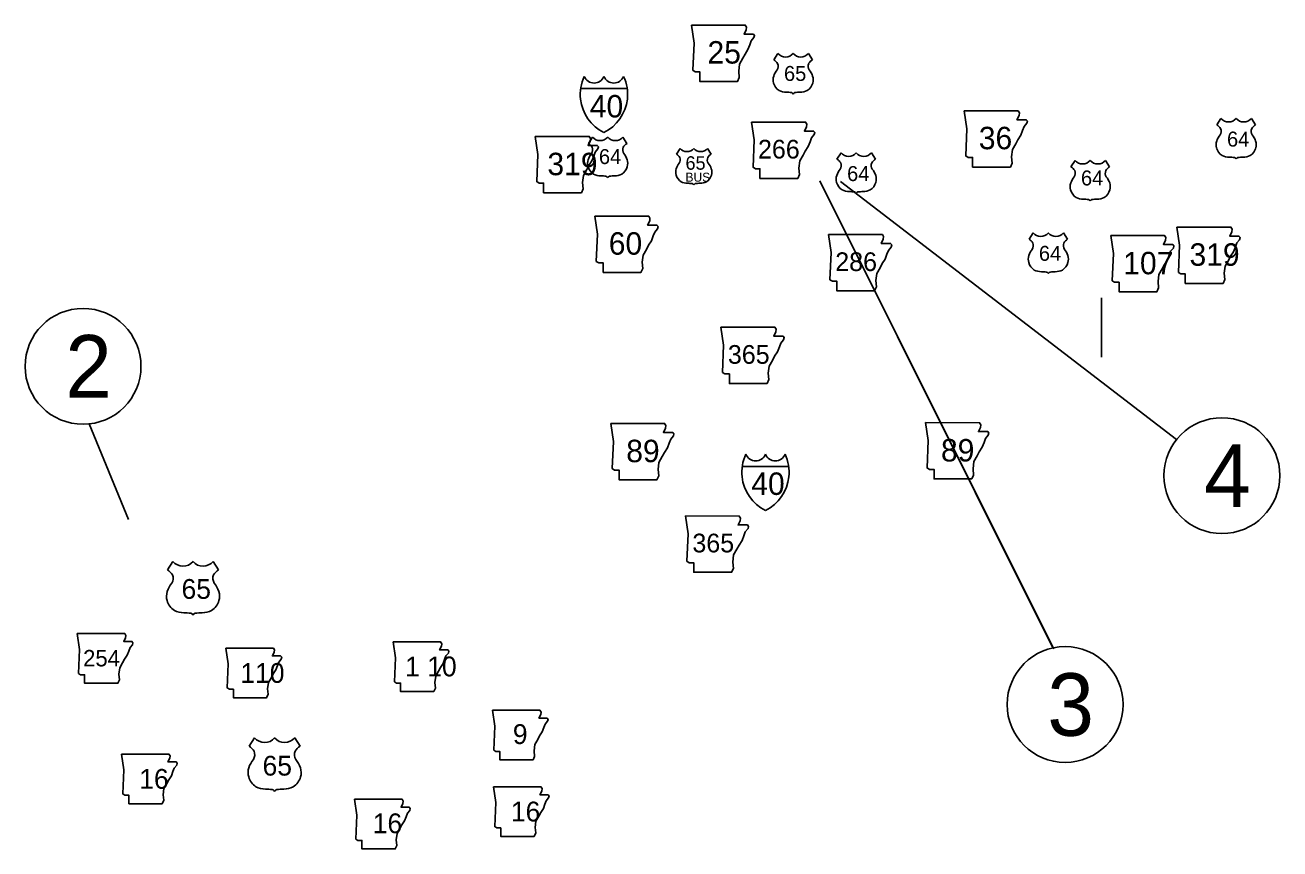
# Model space of a CAD drawing. Extents: x 840176 to 859715, y 1589036 to 1600368.
# Drawn here: x 844901 to 848918, y 1591719 to 1594357 of the extents above; entities that cross this region are included whole.
import ezdxf

# ---------------------------------------------------------------- set-up
doc = ezdxf.new("R2010")
doc.units = 0
for name, color, linetype in [('2', 7, 'Continuous'), ('6', 7, 'Continuous'), ('Default', 7, 'Continuous'), ('DSN_DRFT_Border', 7, 'Continuous'), ('DSN_DRFT_Common-Line', 7, 'Continuous'), ('SHET_Stamp-Prelim', 7, 'Continuous')]:
    doc.layers.add(name, color=color, linetype=linetype)

msp = doc.modelspace()

# ---------------------------------------------------------------- linework, layer by layer
at = {"layer": '2'}
for points in [[(847034.2, 1594357.5), (847042.8, 1594299.9), (847039, 1594212.6), (847046.6, 1594207.8), (847061, 1594207.8), (847061, 1594177.1), (847182, 1594177.1), (847187.7, 1594189.5), (847185.8, 1594209.7), (847188.7, 1594232.7), (847199.2, 1594251), (847206, 1594264.4), (847215.5, 1594278.8), (847221.3, 1594294.2), (847226.1, 1594306.6), (847234.7, 1594317.2), (847236.7, 1594323.9), (847232.8, 1594328.7), (847203.1, 1594328.7), (847209.8, 1594342.1), (847210.8, 1594350.8), (847206.8, 1594357.4)], [(847907.6, 1594083.3), (847916.2, 1594025.7), (847912.4, 1593938.3), (847920.1, 1593933.5), (847934.5, 1593933.5), (847934.5, 1593902.8), (848055.4, 1593902.8), (848061.1, 1593915.3), (848059.2, 1593935.5), (848062.1, 1593958.5), (848072.7, 1593976.7), (848079.4, 1593990.2), (848089, 1594004.6), (848094.7, 1594019.9), (848099.5, 1594032.4), (848108.2, 1594042.9), (848110.1, 1594049.7), (848106.2, 1594054.5), (848076.5, 1594054.5), (848083.2, 1594067.9), (848084.2, 1594076.5), (848080.2, 1594083.2)], [(847227, 1594047), (847235.7, 1593989.4), (847231.8, 1593902.1), (847239.5, 1593897.3), (847253.9, 1593897.3), (847253.9, 1593866.5), (847374.8, 1593866.5), (847380.6, 1593879), (847378.7, 1593899.2), (847381.5, 1593922.2), (847392.1, 1593940.4), (847398.8, 1593953.9), (847408.4, 1593968.3), (847414.2, 1593983.6), (847419, 1593996.1), (847427.6, 1594006.7), (847429.5, 1594013.4), (847425.7, 1594018.2), (847395.9, 1594018.2), (847402.6, 1594031.6), (847403.6, 1594040.2), (847399.6, 1594046.9)], [(846534.5, 1594001), (846543.1, 1593943.4), (846539.3, 1593856.1), (846547, 1593851.3), (846561.4, 1593851.3), (846561.4, 1593820.6), (846682.3, 1593820.6), (846688.1, 1593833.1), (846686.1, 1593853.2), (846689, 1593876.2), (846699.6, 1593894.5), (846706.3, 1593907.9), (846715.9, 1593922.3), (846721.6, 1593937.7), (846726.4, 1593950.1), (846735.1, 1593960.7), (846737, 1593967.4), (846733.2, 1593972.2), (846703.4, 1593972.2), (846710.1, 1593985.6), (846711.1, 1593994.3), (846707.1, 1594000.9)], [(846725.2, 1593745.6), (846733.8, 1593688), (846730, 1593600.7), (846737.7, 1593595.9), (846752.1, 1593595.9), (846752.1, 1593565.2), (846873, 1593565.2), (846878.7, 1593577.6), (846876.8, 1593597.8), (846879.7, 1593620.8), (846890.3, 1593639.1), (846897, 1593652.5), (846906.6, 1593666.9), (846912.3, 1593682.3), (846917.1, 1593694.7), (846925.8, 1593705.3), (846927.7, 1593712), (846923.8, 1593716.8), (846894.1, 1593716.8), (846900.8, 1593730.2), (846901.8, 1593738.9), (846897.8, 1593745.5)], [(848588.7, 1593710.4), (848597.3, 1593652.8), (848593.5, 1593565.5), (848601.1, 1593560.7), (848615.5, 1593560.7), (848615.5, 1593530), (848736.4, 1593530), (848742.2, 1593542.5), (848740.3, 1593562.6), (848743.2, 1593585.7), (848753.7, 1593603.9), (848760.4, 1593617.3), (848770, 1593631.7), (848775.8, 1593647.1), (848780.6, 1593659.5), (848789.2, 1593670.1), (848791.1, 1593676.8), (848787.3, 1593681.6), (848757.6, 1593681.6), (848764.3, 1593695.1), (848765.2, 1593703.7), (848761.3, 1593710.3)], [(847473.1, 1593686.7), (847481.7, 1593629.1), (847477.9, 1593541.7), (847485.6, 1593536.9), (847500, 1593536.9), (847500, 1593506.2), (847620.9, 1593506.2), (847626.6, 1593518.7), (847624.7, 1593538.9), (847627.6, 1593561.9), (847638.2, 1593580.1), (847644.9, 1593593.6), (847654.5, 1593608), (847660.2, 1593623.3), (847665, 1593635.8), (847673.7, 1593646.4), (847675.6, 1593653.1), (847671.8, 1593657.9), (847642, 1593657.9), (847648.7, 1593671.3), (847649.7, 1593679.9), (847645.7, 1593686.6)], [(848376.6, 1593683.6), (848385.2, 1593626), (848381.4, 1593538.7), (848389, 1593533.9), (848403.4, 1593533.9), (848403.4, 1593503.2), (848524.4, 1593503.2), (848530.1, 1593515.7), (848528.2, 1593535.8), (848531.1, 1593558.9), (848541.6, 1593577.1), (848548.4, 1593590.5), (848558, 1593604.9), (848563.7, 1593620.3), (848568.5, 1593632.8), (848577.1, 1593643.3), (848579.1, 1593650), (848575.2, 1593654.8), (848545.5, 1593654.8), (848552.2, 1593668.3), (848553.2, 1593676.9), (848549.2, 1593683.5)], [(847128.9, 1593389.9), (847137.6, 1593332.3), (847133.7, 1593244.9), (847141.4, 1593240.1), (847155.8, 1593240.1), (847155.8, 1593209.4), (847276.7, 1593209.4), (847282.5, 1593221.9), (847280.6, 1593242.1), (847283.4, 1593265.1), (847294, 1593283.3), (847300.7, 1593296.8), (847310.3, 1593311.2), (847316.1, 1593326.5), (847320.9, 1593339), (847329.5, 1593349.5), (847331.4, 1593356.3), (847327.6, 1593361.1), (847297.8, 1593361.1), (847304.6, 1593374.5), (847305.5, 1593383.1), (847301.5, 1593389.8)], [(846776.1, 1593081.6), (846784.7, 1593024), (846780.9, 1592936.7), (846788.5, 1592931.9), (846802.9, 1592931.9), (846802.9, 1592901.2), (846923.9, 1592901.2), (846929.6, 1592913.6), (846927.7, 1592933.8), (846930.6, 1592956.8), (846941.1, 1592975.1), (846947.8, 1592988.5), (846957.4, 1593002.9), (846963.2, 1593018.2), (846968, 1593030.7), (846976.6, 1593041.3), (846978.6, 1593048), (846974.7, 1593052.8), (846945, 1593052.8), (846951.7, 1593066.2), (846952.6, 1593074.9), (846948.7, 1593081.5)], [(847784.2, 1593084), (847792.8, 1593026.4), (847789, 1592939.1), (847796.7, 1592934.3), (847811, 1592934.3), (847811, 1592903.6), (847932, 1592903.6), (847937.7, 1592916), (847935.8, 1592936.2), (847938.7, 1592959.2), (847949.2, 1592977.5), (847956, 1592990.9), (847965.6, 1593005.3), (847971.3, 1593020.6), (847976.1, 1593033.1), (847984.8, 1593043.7), (847986.7, 1593050.4), (847982.8, 1593055.2), (847953.1, 1593055.2), (847959.8, 1593068.6), (847960.8, 1593077.3), (847956.8, 1593083.9)], [(847015, 1592785.1), (847023.6, 1592727.5), (847019.8, 1592640.2), (847027.5, 1592635.4), (847041.9, 1592635.4), (847041.9, 1592604.7), (847162.8, 1592604.7), (847168.6, 1592617.2), (847166.6, 1592637.3), (847169.5, 1592660.3), (847180.1, 1592678.6), (847186.8, 1592692), (847196.4, 1592706.4), (847202.1, 1592721.8), (847206.9, 1592734.2), (847215.6, 1592744.8), (847217.5, 1592751.5), (847213.7, 1592756.3), (847183.9, 1592756.3), (847190.6, 1592769.7), (847191.6, 1592778.4), (847187.6, 1592785)]]:
    msp.add_lwpolyline(points, close=True, dxfattribs=at)
at = {"layer": '6'}
for p, q in [((847311.4, 1594266.6), (847298.3, 1594246.4)), ((847408.8, 1594266.6), (847421.8, 1594246.4)), ((848729.5, 1594058.5), (848716.4, 1594038.2)), ((848826.9, 1594058.5), (848840, 1594038.2)), ((846717.7, 1593998.7), (846704.6, 1593978.4)), ((846815, 1593998.7), (846828.1, 1593978.4)), ((846998.2, 1593962.5), (846986.4, 1593944.2)), ((847085.8, 1593962.5), (847097.6, 1593944.2)), ((847513.3, 1593948.3), (847500.2, 1593928.1)), ((847610.7, 1593948.3), (847623.8, 1593928.1)), ((848262.4, 1593924), (848249.3, 1593903.7)), ((848359.7, 1593924), (848372.8, 1593903.7)), ((848128.3, 1593691.7), (848115.2, 1593671.4)), ((848225.6, 1593691.7), (848238.7, 1593671.4))]:
    msp.add_line(p, q, dxfattribs=at)
for centre, radius, start, end in [((847335.8, 1594287.1), 31.9, 220.075, 319.6701), ((847384.4, 1594287.1), 31.9, 220.3299, 319.925), ((847349.7, 1594178.2), 54.4, 138.9565, 162.6913), ((847281.2, 1594217), 34, 30.7809, 59.9883), ((847288.7, 1594225.9), 23.3, 328.8105, 21.2108), ((847431.5, 1594225.9), 23.3, 158.7892, 211.1895), ((847438.9, 1594217), 34, 120.0117, 149.2191), ((847370.5, 1594178.2), 54.4, 17.3087, 41.0435), ((847331.7, 1594182.6), 35.9, 160.9576, 197.3819), ((847337.6, 1594182.7), 41.6, 195.1074, 237.1312), ((847382.6, 1594182.7), 41.6, 302.8688, 344.8926), ((847388.5, 1594182.6), 35.9, 342.6181, 19.0424), ((847338.3, 1594195.8), 53.4, 244.0771, 269.5779), ((847339.6, 1594044.6), 97.8, 81.1942, 90.9539), ((847351.8, 1594132.3), 9.37, 28.0342, 72.9864), ((847368.4, 1594132.3), 9.37, 107.0136, 151.9658), ((847380.6, 1594044.6), 97.8, 89.0461, 98.8058), ((847381.8, 1594195.8), 53.4, 270.4221, 295.9229), ((848753.9, 1594079), 31.9, 220.075, 319.6701), ((848802.5, 1594079), 31.9, 220.3299, 319.925), ((848699.3, 1594008.8), 34, 30.7809, 59.9883), ((848706.8, 1594017.8), 23.3, 328.8105, 21.2108), ((848849.6, 1594017.8), 23.3, 158.7892, 211.1895), ((848857.1, 1594008.8), 34, 120.0117, 149.2191), ((846687.5, 1593949), 34, 30.7809, 59.9883), ((846742.1, 1594019.2), 31.9, 220.075, 319.6701), ((846790.7, 1594019.2), 31.9, 220.3299, 319.925), ((846845.2, 1593949), 34, 120.0117, 149.2191), ((848749.8, 1593974.5), 35.9, 160.9576, 197.3819), ((848767.8, 1593970), 54.4, 138.9565, 162.6913), ((848788.6, 1593970), 54.4, 17.3087, 41.0435), ((848806.6, 1593974.5), 35.9, 342.6181, 19.0424), ((846756, 1593910.2), 54.4, 138.9565, 162.6913), ((846695, 1593958), 23.3, 328.8105, 21.2108), ((846837.8, 1593958), 23.3, 158.7892, 211.1895), ((846776.8, 1593910.2), 54.4, 17.3087, 41.0435), ((846971, 1593917.8), 30.6, 30.7809, 59.9883), ((846977.7, 1593925.9), 21, 328.8105, 21.2108), ((847020.1, 1593980.9), 28.7, 220.075, 319.6701), ((847063.8, 1593980.9), 28.7, 220.3299, 319.925), ((847106.2, 1593925.9), 21, 158.7892, 211.1895), ((847113, 1593917.8), 30.6, 120.0117, 149.2191), ((847483.1, 1593898.7), 34, 30.7809, 59.9883), ((847537.7, 1593968.9), 31.9, 220.075, 319.6701), ((847586.3, 1593968.9), 31.9, 220.3299, 319.925), ((847640.9, 1593898.7), 34, 120.0117, 149.2191), ((848755.7, 1593974.6), 41.6, 195.1074, 237.1312), ((848756.5, 1593987.7), 53.4, 244.0771, 269.5779), ((848757.7, 1593836.5), 97.8, 81.1942, 90.9539), ((848769.9, 1593924.2), 9.37, 28.0342, 72.9864), ((848786.5, 1593924.2), 9.37, 107.0136, 151.9658), ((848798.7, 1593836.5), 97.8, 89.0461, 98.8058), ((848799.9, 1593987.7), 53.4, 270.4221, 295.9229), ((848800.7, 1593974.6), 41.6, 302.8688, 344.8926), ((846738, 1593914.7), 35.9, 160.9576, 197.3819), ((846743.9, 1593914.8), 41.6, 195.1074, 237.1312), ((846788.9, 1593914.8), 41.6, 302.8688, 344.8926), ((846794.7, 1593914.7), 35.9, 342.6181, 19.0424), ((847016.4, 1593886.9), 32.3, 160.9576, 197.3819), ((847032.6, 1593882.9), 49, 138.9565, 162.6913), ((847051.3, 1593882.9), 49, 17.3087, 41.0435), ((847067.5, 1593886.9), 32.3, 342.6181, 19.0424), ((847551.6, 1593859.9), 54.4, 138.9565, 162.6913), ((847490.6, 1593907.7), 23.3, 328.8105, 21.2108), ((847633.4, 1593907.7), 23.3, 158.7892, 211.1895), ((847572.4, 1593859.9), 54.4, 17.3087, 41.0435), ((848232.2, 1593874.3), 34, 30.7809, 59.9883), ((848239.7, 1593883.3), 23.3, 328.8105, 21.2108), ((848286.8, 1593944.5), 31.9, 220.075, 319.6701), ((848335.4, 1593944.5), 31.9, 220.3299, 319.925), ((848382.5, 1593883.3), 23.3, 158.7892, 211.1895), ((848389.9, 1593874.3), 34, 120.0117, 149.2191), ((846744.6, 1593927.9), 53.4, 244.0771, 269.5779), ((846745.9, 1593776.7), 97.8, 81.1942, 90.9539), ((846758.1, 1593864.4), 9.37, 28.0342, 72.9864), ((846774.7, 1593864.4), 9.37, 107.0136, 151.9658), ((846786.9, 1593776.7), 97.8, 89.0461, 98.8058), ((846788.1, 1593927.9), 53.4, 270.4221, 295.9229), ((847021.7, 1593887), 37.4, 195.1074, 237.1312), ((847022.4, 1593898.7), 48.1, 244.0771, 269.5779), ((847023.5, 1593762.7), 88, 81.1942, 90.9539), ((847034.5, 1593841.6), 8.44, 28.0342, 72.9864), ((847049.4, 1593841.6), 8.44, 107.0136, 151.9658), ((847060.4, 1593762.7), 88, 89.0461, 98.8058), ((847061.5, 1593898.7), 48.1, 270.4221, 295.9229), ((847062.2, 1593887), 37.4, 302.8688, 344.8926), ((847533.6, 1593864.3), 35.9, 160.9576, 197.3819), ((847539.5, 1593864.4), 41.6, 195.1074, 237.1312), ((847584.5, 1593864.4), 41.6, 302.8688, 344.8926), ((847590.4, 1593864.3), 35.9, 342.6181, 19.0424), ((848282.7, 1593840), 35.9, 160.9576, 197.3819), ((848300.7, 1593835.5), 54.4, 138.9565, 162.6913), ((848321.5, 1593835.5), 54.4, 17.3087, 41.0435), ((848339.4, 1593840), 35.9, 342.6181, 19.0424), ((847540.3, 1593877.5), 53.4, 244.0771, 269.5779), ((847541.5, 1593726.3), 97.8, 81.1942, 90.9539), ((847553.7, 1593814), 9.37, 28.0342, 72.9864), ((847570.3, 1593814), 9.37, 107.0136, 151.9658), ((847582.5, 1593726.3), 97.8, 89.0461, 98.8058), ((847583.7, 1593877.5), 53.4, 270.4221, 295.9229), ((848288.6, 1593840.1), 41.6, 195.1074, 237.1312), ((848333.6, 1593840.1), 41.6, 302.8688, 344.8926), ((848289.3, 1593853.2), 53.4, 244.0771, 269.5779), ((848290.6, 1593702), 97.8, 81.1942, 90.9539), ((848302.8, 1593789.7), 9.37, 28.0342, 72.9864), ((848319.3, 1593789.7), 9.37, 107.0136, 151.9658), ((848331.6, 1593702), 97.8, 89.0461, 98.8058), ((848332.8, 1593853.2), 53.4, 270.4221, 295.9229), ((848152.7, 1593712.2), 31.9, 220.075, 319.6701), ((848201.2, 1593712.2), 31.9, 220.3299, 319.925), ((848098.1, 1593642), 34, 30.7809, 59.9883), ((848105.6, 1593651), 23.3, 328.8105, 21.2108), ((848248.3, 1593651), 23.3, 158.7892, 211.1895), ((848255.8, 1593642), 34, 120.0117, 149.2191), ((848148.6, 1593607.7), 35.9, 160.9576, 197.3819), ((848166.5, 1593603.2), 54.4, 138.9565, 162.6913), ((848187.4, 1593603.2), 54.4, 17.3087, 41.0435), ((848205.3, 1593607.7), 35.9, 342.6181, 19.0424), ((848154.4, 1593607.8), 41.6, 195.1074, 237.1312), ((848155.2, 1593620.9), 53.4, 244.0771, 269.5779), ((848156.4, 1593469.7), 97.8, 81.1942, 90.9539), ((848197.4, 1593469.7), 97.8, 89.0461, 98.8058), ((848198.7, 1593620.9), 53.4, 270.4221, 295.9229), ((848199.5, 1593607.8), 41.6, 302.8688, 344.8926), ((848168.7, 1593557.4), 9.37, 28.0342, 72.9864), ((848185.2, 1593557.4), 9.37, 107.0136, 151.9658)]:
    msp.add_arc(centre, radius, start, end, dxfattribs=at)
at = {"layer": 'Default'}
for p, q in [((845374.6, 1592639.2), (845357.2, 1592612.4)), ((845503.2, 1592639.2), (845520.6, 1592612.4)), ((845635.8, 1592074.4), (845618.5, 1592047.6)), ((845764.5, 1592074.4), (845781.8, 1592047.6))]:
    msp.add_line(p, q, dxfattribs=at)
for points in [[(845068.1, 1592408.5), (845075.7, 1592357.7), (845072.3, 1592280.7), (845079.1, 1592276.5), (845091.8, 1592276.5), (845091.8, 1592249.4), (845198.4, 1592249.4), (845203.4, 1592260.4), (845201.7, 1592278.2), (845204.3, 1592298.5), (845213.6, 1592314.6), (845219.5, 1592326.4), (845228, 1592339.1), (845233, 1592352.6), (845237.3, 1592363.6), (845244.9, 1592372.9), (845246.6, 1592378.9), (845243.2, 1592383.1), (845217, 1592383.1), (845222.9, 1592394.9), (845223.7, 1592402.6), (845220.2, 1592408.4)], [(845544.3, 1592362), (845551.9, 1592311.3), (845548.5, 1592234.3), (845555.3, 1592230.1), (845568, 1592230.1), (845568, 1592203), (845674.5, 1592203), (845679.6, 1592214), (845677.9, 1592231.8), (845680.5, 1592252.1), (845689.8, 1592268.1), (845695.7, 1592280), (845704.1, 1592292.7), (845709.2, 1592306.2), (845713.5, 1592317.2), (845721.1, 1592326.5), (845722.8, 1592332.4), (845719.4, 1592336.7), (845693.2, 1592336.7), (845699.1, 1592348.5), (845699.9, 1592356.1), (845696.4, 1592362)], [(846079.6, 1592381.7), (846087.2, 1592330.9), (846083.8, 1592254), (846090.6, 1592249.7), (846103.2, 1592249.7), (846103.2, 1592222.7), (846209.8, 1592222.7), (846214.9, 1592233.7), (846213.2, 1592251.4), (846215.7, 1592271.7), (846225.1, 1592287.8), (846231, 1592299.6), (846239.4, 1592312.3), (846244.5, 1592325.9), (846248.7, 1592336.9), (846256.3, 1592346.2), (846258, 1592352.1), (846254.7, 1592356.3), (846228.4, 1592356.3), (846234.4, 1592368.2), (846235.2, 1592375.8), (846231.7, 1592381.6)], [(846397.2, 1592163.1), (846404.8, 1592112.4), (846401.5, 1592035.4), (846408.2, 1592031.2), (846420.9, 1592031.2), (846420.9, 1592004.1), (846527.5, 1592004.1), (846532.6, 1592015.1), (846530.9, 1592032.9), (846533.4, 1592053.2), (846542.7, 1592069.2), (846548.6, 1592081.1), (846557.1, 1592093.8), (846562.2, 1592107.3), (846566.4, 1592118.3), (846574, 1592127.6), (846575.7, 1592133.5), (846572.3, 1592137.8), (846546.1, 1592137.8), (846552, 1592149.6), (846552.9, 1592157.2), (846549.4, 1592163.1)], [(845209.9, 1592022.5), (845217.5, 1591971.7), (845214.1, 1591894.8), (845220.9, 1591890.5), (845233.5, 1591890.5), (845233.5, 1591863.5), (845340.1, 1591863.5), (845345.2, 1591874.5), (845343.5, 1591892.2), (845346, 1591912.5), (845355.4, 1591928.6), (845361.3, 1591940.4), (845369.7, 1591953.1), (845374.8, 1591966.7), (845379, 1591977.7), (845386.7, 1591987), (845388.3, 1591992.9), (845385, 1591997.1), (845358.7, 1591997.1), (845364.7, 1592009), (845365.5, 1592016.6), (845362, 1592022.4)], [(846400.6, 1591917.7), (846408.3, 1591867), (846404.9, 1591790), (846411.6, 1591785.7), (846424.3, 1591785.7), (846424.3, 1591758.7), (846530.9, 1591758.7), (846536, 1591769.7), (846534.3, 1591787.4), (846536.8, 1591807.7), (846546.1, 1591823.8), (846552.1, 1591835.7), (846560.5, 1591848.3), (846565.6, 1591861.9), (846569.8, 1591872.9), (846577.4, 1591882.2), (846579.1, 1591888.1), (846575.7, 1591892.3), (846549.5, 1591892.3), (846555.4, 1591904.2), (846556.3, 1591911.8), (846552.8, 1591917.6)], [(845956, 1591877.7), (845963.6, 1591827), (845960.2, 1591750), (845967, 1591745.8), (845979.7, 1591745.8), (845979.7, 1591718.7), (846086.2, 1591718.7), (846091.3, 1591729.7), (846089.6, 1591747.4), (846092.2, 1591767.7), (846101.5, 1591783.8), (846107.4, 1591795.7), (846115.8, 1591808.4), (846120.9, 1591821.9), (846125.2, 1591832.9), (846132.8, 1591842.2), (846134.5, 1591848.1), (846131.1, 1591852.3), (846104.9, 1591852.3), (846110.8, 1591864.2), (846111.6, 1591871.8), (846108.1, 1591877.6)]]:
    msp.add_lwpolyline(points, close=True, dxfattribs=at)
for centre, radius, start, end in [((845334.6, 1592573.6), 45, 30.7809, 59.9883), ((845406.8, 1592666.3), 42.1, 220.075, 319.6701), ((845471, 1592666.3), 42.1, 220.3299, 319.925), ((845543.2, 1592573.6), 45, 120.0117, 149.2191), ((845425.1, 1592522.2), 71.9, 138.9565, 162.6913), ((845344.5, 1592585.4), 30.8, 328.8105, 21.2108), ((845533.3, 1592585.4), 30.8, 158.7892, 211.1895), ((845452.7, 1592522.2), 71.9, 17.3087, 41.0435), ((845401.4, 1592528.1), 47.5, 160.9576, 197.3819), ((845476.4, 1592528.1), 47.5, 342.6181, 19.0424), ((845409.1, 1592528.3), 55, 195.1074, 237.1312), ((845410.2, 1592545.6), 70.6, 244.0771, 269.5779), ((845467.6, 1592545.6), 70.6, 270.4221, 295.9229), ((845468.7, 1592528.3), 55, 302.8688, 344.8926), ((845411.8, 1592345.7), 129.3, 81.1942, 90.9539), ((845428, 1592461.6), 12.4, 28.0342, 72.9864), ((845449.8, 1592461.6), 12.4, 107.0136, 151.9658), ((845466, 1592345.7), 129.3, 89.0461, 98.8058), ((845595.8, 1592008.8), 45, 30.7809, 59.9883), ((845668, 1592101.5), 42.1, 220.075, 319.6701), ((845732.2, 1592101.5), 42.1, 220.3299, 319.925), ((845804.4, 1592008.8), 45, 120.0117, 149.2191), ((845686.3, 1591957.4), 71.9, 138.9565, 162.6913), ((845605.7, 1592020.6), 30.8, 328.8105, 21.2108), ((845794.5, 1592020.6), 30.8, 158.7892, 211.1895), ((845713.9, 1591957.4), 71.9, 17.3087, 41.0435), ((845662.6, 1591963.3), 47.5, 160.9576, 197.3819), ((845737.6, 1591963.3), 47.5, 342.6181, 19.0424), ((845670.3, 1591963.5), 55, 195.1074, 237.1312), ((845729.9, 1591963.5), 55, 302.8688, 344.8926), ((845671.4, 1591980.8), 70.6, 244.0771, 269.5779), ((845673, 1591780.9), 129.3, 81.1942, 90.9539), ((845689.2, 1591896.8), 12.4, 28.0342, 72.9864), ((845711, 1591896.8), 12.4, 107.0136, 151.9658), ((845727.2, 1591780.9), 129.3, 89.0461, 98.8058), ((845728.9, 1591980.8), 70.6, 270.4221, 295.9229)]:
    msp.add_arc(centre, radius, start, end, dxfattribs=at)
at = {"layer": 'DSN_DRFT_Border'}
for points in [[(847445.4, 1593858.4), (848194.5, 1592359.9)], [(848191.7, 1592362.6), (847445.4, 1593858.4)], [(848587.3, 1593029.7), (847512, 1593856.9)], [(845232.4, 1592773.8), (845106.3, 1593080.6)], [(845232.4, 1592773.8), (845106.3, 1593080.6)]]:
    msp.add_lwpolyline(points, dxfattribs=at)
for centre in [(845086.9, 1593264.4), (848732.7, 1592914.3), (848230.6, 1592181.1)]:
    msp.add_circle(centre, 185.5, dxfattribs=at)
at = {"layer": 'DSN_DRFT_Common-Line'}
for p, q in [((846680.1, 1594153.9), (846828.8, 1594153.9)), ((847197.1, 1592943.7), (847345.8, 1592943.7))]:
    msp.add_line(p, q, dxfattribs=at)
for centre, radius, start, end in [((846818.3, 1594134.5), 139.6, 155.2204, 185.7928), ((846723, 1594205.8), 34, 202.1459, 337.3414), ((846785.8, 1594205.8), 34, 202.6586, 337.8541), ((846690.6, 1594134.5), 139.6, 354.2072, 24.7796), ((846815.7, 1594135.7), 137.1, 186.3923, 243.4571), ((846693.1, 1594135.7), 137.1, 296.5429, 353.6077), ((847335.3, 1592924.4), 139.6, 155.2204, 185.7928), ((847240.1, 1592995.7), 34, 202.1459, 337.3414), ((847302.8, 1592995.7), 34, 202.6586, 337.8541), ((847207.6, 1592924.4), 139.6, 354.2072, 24.7796), ((847332.7, 1592925.6), 137.1, 186.3923, 243.4571), ((847210.2, 1592925.6), 137.1, 296.5429, 353.6077)]:
    msp.add_arc(centre, radius, start, end, dxfattribs=at)
at = {"layer": 'SHET_Stamp-Prelim'}
msp.add_line((848346.8, 1593293.8), (848346.8, 1593483.4), dxfattribs=at)

# ---------------------------------------------------------------- texts
at = {"layer": '2'}
for s, height, p in [('25', 71.88, (847085.8, 1594234.2)), ('36', 71.88, (847954.4, 1593959.8)), ('266', 59.9, (847247.5, 1593930.1)), ('319', 71.88, (846573.4, 1593876.6)), ('60', 71.88, (846769.8, 1593622.1)), ('319', 71.88, (848628.9, 1593586.6)), ('286', 59.9, (847494.9, 1593569.6)), ('107', 71.88, (848416.8, 1593559.3)), ('365', 59.9, (847151.1, 1593272.6)), ('89', 71.88, (846825.8, 1592957.4)), ('89', 71.88, (847833.3, 1592959.7)), ('365', 59.9, (847037.5, 1592668.5))]:
    msp.add_text(s, height=height, dxfattribs=at).set_placement(p)
at = {"layer": '6'}
for s, height, p in [('65', 47.92, (847330.8, 1594178.6)), ('64', 47.92, (848749, 1593968.3)), ('64', 47.92, (846738.3, 1593912.3)), ('65', 43.13, (847015.5, 1593894.2)), ('64', 47.92, (847532.8, 1593857.9)), ('64', 47.92, (848281.4, 1593843.9)), ('BUS', 28.75, (847015.5, 1593855.9)), ('64', 47.92, (848146.7, 1593602.4))]:
    msp.add_text(s, height=height, dxfattribs=at).set_placement(p)
at = {"layer": 'Default'}
for s, height, p in [('65', 63.36, (845402.2, 1592519.7)), ('254', 52.8, (845087.1, 1592303.3)), ('1 10', 63.36, (846118, 1592271.4)), ('110', 63.36, (845590.5, 1592250.6)), ('9', 63.4, (846462.8, 1592054.7)), ('65', 63.36, (845661.6, 1591953.6)), ('16', 63.36, (845266.8, 1591911.4)), ('16', 63.36, (846456.5, 1591806.8)), ('16', 63.36, (846014.3, 1591769.1))]:
    msp.add_text(s, height=height, dxfattribs=at).set_placement(p)
at = {"layer": 'DSN_DRFT_Border'}
for s, p in [('2', (845030.1, 1593164.2)), ('4', (848675.9, 1592814.1)), ('3', (848173.8, 1592081))]:
    msp.add_text(s, height=200.4, dxfattribs=at).set_placement(p)
at = {"layer": 'DSN_DRFT_Common-Line'}
for p in [(846709.1, 1594061.6), (847226.1, 1592852.6)]:
    msp.add_text('40', height=71.88, dxfattribs=at).set_placement(p)

doc.saveas('drawing.dxf')
